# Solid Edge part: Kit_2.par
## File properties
Author: bmolnar
Last saved by: bmolnar
Revision: 76
Sűrűség: 0,000 kg/m^3
Pontosság: 0,990
Username: bmolnar
Dokumentum tartalom típus: 0
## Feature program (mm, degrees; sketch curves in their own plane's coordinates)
base feature "unnamed BaseFeature 1"
sketch for "Furat_1" plane through (-18.15, -81.65, 0) normal (1, 0, 0) x-axis (0, 0, -1)
  hole centre (0, 13.85) bore radius 2.067
hole "Furat_1" nominal diameter 5 finite  ThreadDepth = 5 mm; StartChamferOffset = 0.5 mm; StartChamferAngle = 45 deg
sketch for "Furat_2" plane through (11, -70.2, -11) normal (0, -1, 0) x-axis (0, 0, 1)
  hole centre (0, 0) bore radius 2.067
hole "Furat_2" nominal diameter 5
sketch for "unnamed Hole 1" plane through (11, -70.2, -11) normal (0, -1, 0) x-axis (0, 0, 1)
  hole centre (22, 0) bore radius 2.067
hole "unnamed Hole 1"
sketch for "unnamed Hole 2" plane through (11, -70.2, -11) normal (0, -1, 0) x-axis (0, 0, 1)
  hole centre (22, 22) bore radius 2.067
hole "unnamed Hole 2"
sketch for "unnamed Hole 3" plane through (11, -70.2, -11) normal (0, -1, 0) x-axis (0, 0, 1)
  hole centre (0, 22) bore radius 2.067
hole "unnamed Hole 3"
pattern "unnamed Pattern 1" of "Furat_2", "unnamed Hole 1", "unnamed Hole 2", "unnamed Hole 3"
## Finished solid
Body 1: solid body, 258 faces, 616 edges, 372 vertices, 2 internal voids.
  Faces by surface: plane 124, cylinder 58, swept 43, cone 26, torus 7
  Edges by curve: line 361, circle 155, spline 90, curve on surface 5, intersection 4, ellipse 1
Bounding box of the edges (mm; curved faces can reach further): 36.300 x 11.800 x 36.300, from (-18.15, -75.3, -18.15) to (18.15, -63.5, 18.15).
Cylindrical faces by radius (mm): R0.2 x18, R0.4307 x1, R0.4865 x1, R2.067 x5, R3.75 x2, R4 x4, R4.1 x12, R5.24 x1, R5.45 x2, R5.55 x2, R5.7 x1, R6 x1, R6.92 x1, R7 x1, R11.25 x6
Conical faces (half-angle, radius in mm at the cone's reference point): 0.5 deg R4.5 x4, 3 deg R6.96 x1, 7 deg R6.4156 x1, 14 deg R5.12 x1, 14 deg R5.3801 x1, 17 deg R5.12 x1, 23 deg R5.7369 x1, 42.5 deg R5.1096 x1, 45 deg R2.317 x2, 45 deg R2.367 x2, 45 deg R2.567 x1, 45 deg R4.25 x2, 45 deg R5.3 x2, 45 deg R5.35 x2, 45 deg R5.85 x1, 84 deg R5.4096 x1, 85 deg R6.73 x1, 87 deg R5.1371 x1
Toroidal faces (ring radius, tube radius in mm): R3.8 r0.2 x2, R4.4 r0.4 x2, R5.6606 r0.18 x1, R6.1131 r0.26 x1, R6.72 r0.2 x1
Planar faces by outward normal: +x 5, +y 4, +z 15, -x 7, -y 16, -z 13, oblique 64
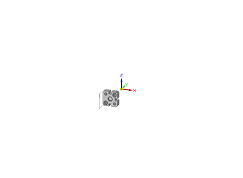
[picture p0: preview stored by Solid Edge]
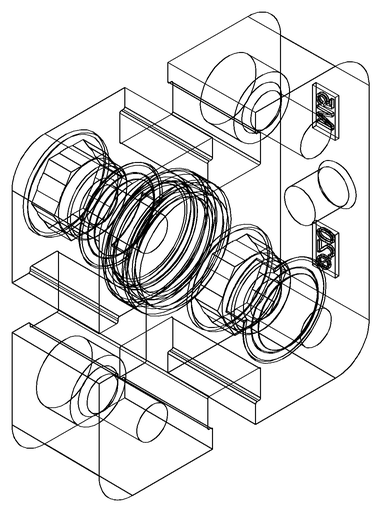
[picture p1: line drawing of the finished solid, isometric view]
